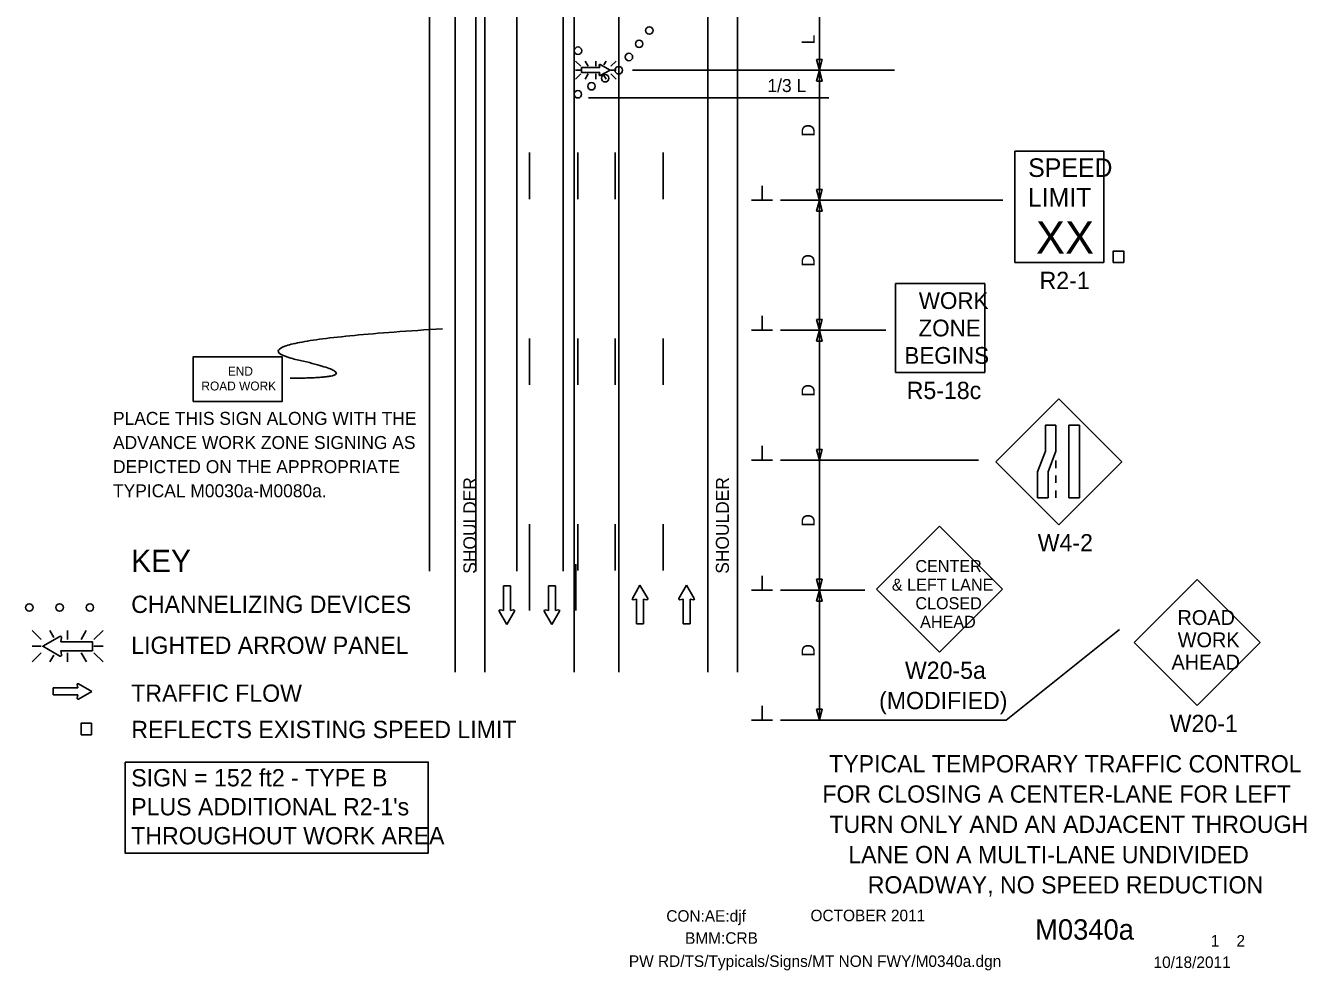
# Model space of a CAD drawing. Extents: x 16743 to 18475, y 7218 to 8262.
# Drawn here: x 16746 to 17435, y 7218 to 7727 of the extents above; entities that cross this region are included whole.
import ezdxf

# ---------------------------------------------------------------- set-up
doc = ezdxf.new("R2010")
doc.units = 0
for name, color, linetype in [('ALI_LEGAL_EX', 7, 'Continuous'), ('BORDER_SIGNAL_WO', 7, 'Continuous'), ('MT_SCRATCH_LEVEL_E', 7, 'Continuous'), ('PAVT_EDGE_EX', 7, 'Continuous'), ('TRAFFIC_SIGNS_PR', 7, 'Continuous'), ('TYPICAL_TEXT_DIMEN_EX', 7, 'Continuous'), ('TYPICAL_TEXT_DIMEN_PR', 7, 'Continuous')]:
    doc.layers.add(name, color=color, linetype=linetype)

msp = doc.modelspace()

# ---------------------------------------------------------------- linework, layer by layer
at = {"layer": 'ALI_LEGAL_EX'}
for points in [[(17017.08, 7658.47), (17017.08, 7633.47)], [(17043.08, 7658.47), (17043.08, 7633.47)], [(17063.08, 7658.47), (17063.08, 7633.47)], [(17089.08, 7658.47), (17089.08, 7633.47)], [(17017.08, 7558.47), (17017.08, 7533.47)], [(17043.08, 7558.47), (17043.08, 7533.47)], [(17063.08, 7558.47), (17063.08, 7533.47)], [(17089.08, 7558.47), (17089.08, 7533.47)], [(17017.08, 7458.47), (17017.08, 7433.47)], [(17043.08, 7458.47), (17043.08, 7433.47)], [(17063.08, 7458.47), (17063.08, 7433.47)], [(17089.08, 7458.47), (17089.08, 7433.47)]]:
    msp.add_lwpolyline(points, dxfattribs=at)
at = {"layer": 'MT_SCRATCH_LEVEL_E'}
for p, q in [((17006.75, 7425.14), (17003.01, 7425.14)), ((17003.01, 7425.14), (17003.01, 7411.89)), ((17006.75, 7425.14), (17003.01, 7425.14)), ((17003.01, 7425.14), (17003.01, 7411.89)), ((17006.75, 7411.89), (17006.75, 7425.14)), ((17006.75, 7411.89), (17006.75, 7425.14)), ((17031.01, 7425.14), (17027.26, 7425.14)), ((17027.26, 7425.14), (17027.26, 7411.89)), ((17031.01, 7425.14), (17027.26, 7425.14)), ((17027.26, 7425.14), (17027.26, 7411.89)), ((17031.01, 7411.89), (17031.01, 7425.14)), ((17031.01, 7411.89), (17031.01, 7425.14)), ((17076.52, 7425.6), (17072.41, 7418.36)), ((17076.52, 7425.6), (17072.41, 7418.36)), ((17080.67, 7418.36), (17076.52, 7425.6)), ((17080.67, 7418.36), (17076.52, 7425.6)), ((17101.61, 7425.6), (17097.5, 7418.36)), ((17101.61, 7425.6), (17097.5, 7418.36)), ((17105.75, 7418.36), (17101.61, 7425.6)), ((17105.75, 7418.36), (17101.61, 7425.6)), ((17072.89, 7417.68), (17074.67, 7417.99)), ((17072.89, 7417.68), (17074.67, 7417.99)), ((17074.67, 7417.99), (17074.67, 7404.74)), ((17074.67, 7417.99), (17074.67, 7404.74)), ((17078.41, 7404.74), (17078.41, 7417.99)), ((17078.41, 7417.99), (17080.19, 7417.68)), ((17078.41, 7404.74), (17078.41, 7417.99)), ((17078.41, 7417.99), (17080.19, 7417.68)), ((17097.98, 7417.68), (17099.76, 7417.99)), ((17097.98, 7417.68), (17099.76, 7417.99)), ((17099.76, 7417.99), (17099.76, 7404.74)), ((17099.76, 7417.99), (17099.76, 7404.74)), ((17103.5, 7404.74), (17103.5, 7417.99)), ((17103.5, 7417.99), (17105.28, 7417.68)), ((17103.5, 7404.74), (17103.5, 7417.99)), ((17103.5, 7417.99), (17105.28, 7417.68)), ((17000.75, 7411.52), (17004.9, 7404.28)), ((17000.75, 7411.52), (17004.9, 7404.28)), ((17003.01, 7411.89), (17001.23, 7412.2)), ((17003.01, 7411.89), (17001.23, 7412.2)), ((17004.9, 7404.28), (17009.01, 7411.52)), ((17004.9, 7404.28), (17009.01, 7411.52)), ((17008.53, 7412.2), (17006.75, 7411.89)), ((17008.53, 7412.2), (17006.75, 7411.89)), ((17025.01, 7411.52), (17029.15, 7404.28)), ((17025.01, 7411.52), (17029.15, 7404.28)), ((17027.26, 7411.89), (17025.49, 7412.2)), ((17027.26, 7411.89), (17025.49, 7412.2)), ((17029.15, 7404.28), (17033.27, 7411.52)), ((17029.15, 7404.28), (17033.27, 7411.52)), ((17032.78, 7412.2), (17031.01, 7411.89)), ((17032.78, 7412.2), (17031.01, 7411.89)), ((17074.67, 7404.74), (17078.41, 7404.74)), ((17074.67, 7404.74), (17078.41, 7404.74)), ((17099.76, 7404.74), (17103.5, 7404.74)), ((17099.76, 7404.74), (17103.5, 7404.74)), ((16773.88, 7370.22), (16760.62, 7370.22)), ((16760.62, 7370.22), (16760.62, 7366.48)), ((16773.88, 7370.22), (16760.62, 7370.22)), ((16760.62, 7370.22), (16760.62, 7366.48)), ((16773.56, 7372), (16773.88, 7370.22)), ((16773.56, 7372), (16773.88, 7370.22)), ((16781.48, 7368.37), (16774.24, 7372.48)), ((16781.48, 7368.37), (16774.24, 7372.48)), ((16760.62, 7366.48), (16773.88, 7366.48)), ((16760.62, 7366.48), (16773.88, 7366.48)), ((16773.88, 7366.48), (16773.56, 7364.7)), ((16773.88, 7366.48), (16773.56, 7364.7)), ((16774.24, 7364.22), (16781.48, 7368.37)), ((16774.24, 7364.22), (16781.48, 7368.37))]:
    msp.add_line(p, q, dxfattribs=at)
for centre, start, end in [((17072.81, 7418.14), 150.42484, 279.96381), ((17072.81, 7418.14), 150.42484, 279.96381), ((17080.26, 7418.14), 260.03619, 29.77312), ((17080.26, 7418.14), 260.03619, 29.77312), ((17097.9, 7418.14), 150.42484, 279.96381), ((17097.9, 7418.14), 150.42484, 279.96381), ((17105.34, 7418.14), 260.03619, 29.77312), ((17105.34, 7418.14), 260.03619, 29.77312), ((17001.16, 7411.74), 80.03619, 209.77312), ((17001.16, 7411.74), 80.03619, 209.77312), ((17008.6, 7411.74), 330.42484, 99.96381), ((17008.6, 7411.74), 330.42484, 99.96381), ((17025.42, 7411.74), 80.03619, 209.77312), ((17025.42, 7411.74), 80.03619, 209.77312), ((17032.86, 7411.74), 330.42484, 99.96381), ((17032.86, 7411.74), 330.42484, 99.96381), ((16774.02, 7372.07), 60.42484, 189.96381), ((16774.02, 7372.07), 60.42484, 189.96381), ((16774.02, 7364.63), 170.03619, 299.77312), ((16774.02, 7364.63), 170.03619, 299.77312)]:
    msp.add_arc(centre, 0.463, start, end, dxfattribs=at)
at = {"layer": 'PAVT_EDGE_EX'}
for p, q in [((16963.15, 8262.34), (16963.15, 7433.15)), ((16988.15, 8262.34), (16988.15, 7433.15)), ((17010.15, 8262.34), (17010.15, 7433.15)), ((17035.15, 8262.34), (17035.15, 7433.15)), ((16977.08, 8216.25), (16977.08, 7378.68)), ((16993.08, 8216.25), (16993.08, 7378.68)), ((17041.08, 8216.25), (17041.08, 7378.68)), ((17065.08, 8216.25), (17065.08, 7378.68)), ((17113.08, 8216.25), (17113.08, 7378.68)), ((17129.08, 8216.25), (17129.08, 7378.68))]:
    msp.add_line(p, q, dxfattribs=at)
for points in [[(17017.08, 7411.93), (17017.08, 7436.93)], [(17042.08, 7411.93), (17042.08, 7436.93)]]:
    msp.add_lwpolyline(points, dxfattribs=at)
at = {"layer": 'TRAFFIC_SIGNS_PR'}
for p, q in [((17044.7, 7705), (17041.88, 7707.82)), ((17047, 7707.82), (17048.62, 7705)), ((17052.78, 7705), (17052.78, 7707.82)), ((17058.25, 7707.82), (17057.05, 7705.72)), ((17063.69, 7707.82), (17060.87, 7705)), ((17044.7, 7702.97), (17041.88, 7702.97)), ((17044.7, 7700.93), (17041.88, 7698.11)), ((17048.65, 7700.93), (17047.02, 7698.11)), ((17052.78, 7700.93), (17052.78, 7698.11)), ((17056.97, 7700.3), (17058.23, 7698.11)), ((17060.87, 7702.97), (17063.69, 7702.97)), ((17063.69, 7698.11), (17060.87, 7700.93)), ((17278.25, 7659.32), (17326.25, 7659.32)), ((17278.25, 7599.32), (17278.25, 7659.32)), ((17326.25, 7599.32), (17326.25, 7659.32)), ((17278.25, 7599.32), (17326.25, 7599.32)), ((17214.07, 7540.09), (17214.07, 7588.09)), ((17214.07, 7588.09), (17262.07, 7588.09)), ((17262.07, 7540.09), (17262.07, 7588.09)), ((17214.07, 7540.09), (17262.07, 7540.09)), ((17301.9, 7525.93), (17267.96, 7491.99)), ((17335.84, 7491.99), (17301.9, 7525.93)), ((17267.96, 7491.99), (17301.9, 7458.05)), ((17300.34, 7492.61), (17300.34, 7488.61)), ((17301.9, 7458.05), (17335.84, 7491.99)), ((17300.34, 7484.61), (17300.34, 7480.61)), ((17300.34, 7476.61), (17300.34, 7472.61)), ((17237.71, 7457.26), (17203.76, 7423.32)), ((17271.65, 7423.32), (17237.71, 7457.26)), ((17376.38, 7428.63), (17342.44, 7394.69)), ((17410.33, 7394.69), (17376.38, 7428.63)), ((17203.76, 7423.32), (17237.71, 7389.38)), ((17237.71, 7389.38), (17271.65, 7423.32)), ((16749.35, 7401.18), (16754.28, 7396.24)), ((16761.11, 7397.36), (16758.9, 7401.18)), ((16768.43, 7396.24), (16768.43, 7401.18)), ((16775.67, 7396.24), (16778.52, 7401.18)), ((16782.58, 7396.24), (16787.52, 7401.18)), ((16754.28, 7392.69), (16749.35, 7392.69)), ((16782.58, 7392.69), (16787.52, 7392.69)), ((17342.44, 7394.69), (17376.38, 7360.74)), ((17376.38, 7360.74), (17410.33, 7394.69)), ((16749.35, 7384.2), (16754.28, 7389.13)), ((16758.86, 7384.2), (16760.97, 7387.86)), ((16768.43, 7389.13), (16768.43, 7384.2)), ((16778.56, 7384.2), (16775.71, 7389.13)), ((16782.58, 7389.13), (16787.52, 7384.2))]:
    msp.add_line(p, q, dxfattribs=at)
for points in [[(17054.61, 7705.65), (17054.84, 7704.35), (17045.12, 7704.35), (17045.12, 7701.61), (17054.84, 7701.61), (17054.61, 7700.3)], [(17055.11, 7699.95), (17060.42, 7702.97), (17055.11, 7706.01)], [(16764.36, 7397.96), (16755.07, 7392.69), (16764.36, 7387.37)], [(16765.23, 7388), (16764.83, 7390.26), (16781.85, 7390.26), (16781.85, 7395.07), (16764.83, 7395.07), (16765.24, 7397.35)]]:
    msp.add_lwpolyline(points, dxfattribs=at)
for points in [[(17331.27, 7599.32), (17336.86, 7599.32), (17336.86, 7605.49), (17331.27, 7605.49)], [(16835.95, 7524.48), (16883.95, 7524.48), (16883.95, 7548.48), (16835.95, 7548.48)], [(17300.34, 7511.66), (17300.34, 7497.69), (17296.16, 7486.58), (17296.16, 7472.61), (17290.54, 7472.61), (17290.54, 7486.58), (17294.72, 7497.69), (17294.72, 7511.66)], [(17313.01, 7511.66), (17313.01, 7472.61), (17307.39, 7472.61), (17307.39, 7511.66)], [(16775.69, 7345.03), (16781.28, 7345.03), (16781.28, 7351.2), (16775.69, 7351.2)]]:
    msp.add_lwpolyline(points, close=True, dxfattribs=at)
for centre in [(17081.56, 7724.23), (17043.18, 7713.37), (17076.07, 7717.1), (17070.57, 7709.97), (17057.75, 7698.54), (17065.08, 7702.84), (17050.42, 7694.23), (17043.1, 7689.92), (16747.86, 7413.53), (16764.16, 7413.53), (16780.46, 7413.53)]:
    msp.add_circle(centre, 2, dxfattribs=at)
for centre, radius, start, end in [((17054.95, 7705.71), 0.341, 61.48329, 189.95933), ((17054.95, 7700.25), 0.341, 170.73078, 298.89165), ((16764.65, 7397.44), 0.598, 350.73078, 118.89165), ((16764.65, 7387.89), 0.597, 241.48329, 9.95933)]:
    msp.add_arc(centre, radius, start, end, dxfattribs=at)
msp.add_open_spline([(16888.26, 7537.03), (16935.5, 7537.03), (16850.48, 7556.38), (16970.27, 7563.62)], degree=2, dxfattribs=at)
at = {"layer": 'TYPICAL_TEXT_DIMEN_EX'}
msp.add_lwpolyline([(16799.36, 7330.3), (16962.52, 7330.3), (16962.52, 7281.28), (16799.36, 7281.28)], close=True, dxfattribs=at)
at = {"layer": 'TYPICAL_TEXT_DIMEN_PR'}
for p, q in [((17173.08, 7702.84), (17173.08, 7733.42)), ((17173.08, 7702.84), (17171.51, 7708.7)), ((17171.51, 7708.7), (17173.08, 7708.7)), ((17173.08, 7708.7), (17174.65, 7708.7)), ((17174.65, 7708.7), (17173.08, 7702.84)), ((17213.45, 7702.84), (17072.44, 7702.84)), ((17171.51, 7696.98), (17173.08, 7702.84)), ((17173.08, 7702.84), (17173.08, 7632.84)), ((17173.08, 7702.84), (17174.65, 7696.98)), ((17173.08, 7696.98), (17171.51, 7696.98)), ((17174.65, 7696.98), (17173.08, 7696.98)), ((17178.08, 7687.92), (17048.76, 7687.92)), ((17142.21, 7632.84), (17142.21, 7640.63)), ((17173.08, 7632.84), (17171.51, 7638.7)), ((17171.51, 7638.7), (17173.08, 7638.7)), ((17173.08, 7638.7), (17174.65, 7638.7)), ((17174.65, 7638.7), (17173.08, 7632.84)), ((17147.83, 7632.84), (17136.58, 7632.84)), ((17271.79, 7632.84), (17152.08, 7632.84)), ((17171.51, 7626.98), (17173.08, 7632.84)), ((17171.51, 7626.98), (17173.08, 7632.84)), ((17173.08, 7632.84), (17173.08, 7562.84)), ((17173.08, 7632.84), (17174.65, 7626.98)), ((17173.08, 7632.84), (17174.65, 7626.98)), ((17173.08, 7626.98), (17171.51, 7626.98)), ((17173.08, 7626.98), (17171.51, 7626.98)), ((17174.65, 7626.98), (17173.08, 7626.98)), ((17174.65, 7626.98), (17173.08, 7626.98)), ((17142.21, 7562.84), (17142.21, 7570.63)), ((17147.83, 7562.84), (17136.58, 7562.84)), ((17208.78, 7562.84), (17152.08, 7562.84)), ((17173.08, 7562.84), (17171.51, 7568.7)), ((17171.51, 7568.7), (17173.08, 7568.7)), ((17171.51, 7556.98), (17173.08, 7562.84)), ((17173.08, 7568.7), (17174.65, 7568.7)), ((17174.65, 7568.7), (17173.08, 7562.84)), ((17173.08, 7562.84), (17173.08, 7492.84)), ((17173.08, 7562.84), (17174.65, 7556.98)), ((17173.08, 7556.98), (17171.51, 7556.98)), ((17174.65, 7556.98), (17173.08, 7556.98)), ((17142.21, 7492.84), (17142.21, 7500.63)), ((17173.08, 7492.84), (17171.51, 7498.7)), ((17171.51, 7498.7), (17173.08, 7498.7)), ((17173.08, 7498.7), (17174.65, 7498.7)), ((17174.65, 7498.7), (17173.08, 7492.84)), ((17147.83, 7492.84), (17136.58, 7492.84)), ((17258.69, 7492.84), (17152.08, 7492.84)), ((17173.08, 7492.84), (17173.08, 7422.84)), ((17142.21, 7422.84), (17142.21, 7430.63)), ((17173.08, 7422.84), (17171.51, 7428.7)), ((17171.51, 7428.7), (17173.08, 7428.7)), ((17173.08, 7428.7), (17174.65, 7428.7)), ((17174.65, 7428.7), (17173.08, 7422.84)), ((17147.83, 7422.84), (17136.58, 7422.84)), ((17197.57, 7422.84), (17152.08, 7422.84)), ((17171.51, 7416.98), (17173.08, 7422.84)), ((17173.08, 7422.84), (17173.08, 7352.84)), ((17173.08, 7422.84), (17174.65, 7416.98)), ((17173.08, 7416.98), (17171.51, 7416.98)), ((17174.65, 7416.98), (17173.08, 7416.98)), ((17273.68, 7352.84), (17334.52, 7401.61)), ((17142.21, 7352.84), (17142.21, 7360.63)), ((17173.08, 7352.84), (17171.51, 7358.7)), ((17171.51, 7358.7), (17173.08, 7358.7)), ((17173.08, 7358.7), (17174.65, 7358.7)), ((17174.65, 7358.7), (17173.08, 7352.84)), ((17147.83, 7352.84), (17136.58, 7352.84)), ((17273.68, 7352.84), (17152.08, 7352.84))]:
    msp.add_line(p, q, dxfattribs=at)

# ---------------------------------------------------------------- texts
at = {"layer": 'BORDER_SIGNAL_WO'}
for s, height, p in [('TYPICAL TEMPORARY TRAFFIC CONTROL', 9.3, (17178.31, 7324.72)), ('FOR CLOSING A CENTER-LANE FOR LEFT', 9.3, (17174.71, 7308.42)), ('TURN ONLY AND AN ADJACENT THROUGH', 9.3, (17178.47, 7292.12)), ('LANE ON A MULTI-LANE UNDIVIDED', 9.3, (17188.63, 7275.82)), ('ROADWAY, NO SPEED REDUCTION', 9.3, (17199.12, 7259.52)), ('CON:AE:djf', 6.2, (17090.69, 7244.31)), ('    OCTOBER 2011    ', 6.2, (17159.08, 7244.59)), ('    M0340a   ', 11, (17272.86, 7234.63)), ('BMM:CRB   ', 6.2, (17100.81, 7232.42)), (' 1    2 ', 6.2, (17381.45, 7230.95)), ('PW RD/TS/Typicals/Signs/MT NON FWY/M0340a.dgn    ', 6.2, (17070.55, 7219.96)), ('10/18/2011    ', 6.2, (17352.93, 7219.38))]:
    msp.add_text(s, height=height, dxfattribs=at).set_placement(p)
at = {"layer": 'TRAFFIC_SIGNS_PR'}
for s, height, p in [('SPEED', 10, (17285.46, 7645.4)), ('LIMIT', 10, (17285.26, 7629.4)), ('XX', 17.538, (17289.64, 7604.02)), ('R2-1', 9.3, (17291.6, 7585.02)), ('WORK', 9.021, (17226.57, 7574.3)), ('ZONE', 9.021, (17226.42, 7559.53)), ('BEGINS', 9.021, (17218.83, 7544.77)), ('END', 4.789, (16854.71, 7538.39)), ('ROAD WORK', 4.789, (16840.47, 7530.41)), ('R5-18c', 9.3, (17220.08, 7525.79)), ('PLACE THIS SIGN ALONG WITH THE', 7, (16792.9, 7511.87)), ('ADVANCE WORK ZONE SIGNING AS', 7, (16792.9, 7498.87)), ('DEPICTED ON THE APPROPRIATE', 7, (16792.9, 7485.87)), ('TYPICAL M0030a-M0080a.', 7, (16792.9, 7472.87)), ('W4-2', 9.3, (17290.6, 7443.75)), ('CENTER', 6.5, (17224.75, 7432.57)), ('& LEFT LANE', 6.5, (17212.09, 7422.57)), ('CLOSED', 6.5, (17224.75, 7412.57)), ('ROAD', 8, (17365.81, 7404.11)), ('AHEAD', 6.5, (17227.28, 7402.57)), ('WORK', 8, (17365.95, 7392.11)), ('W20-5a', 9.3, (17219.13, 7375.07)), ('AHEAD', 8, (17362.58, 7380.11)), ('(MODIFIED)', 9.3, (17205.2, 7358.78)), ('W20-1', 9.3, (17361.6, 7346.45))]:
    msp.add_text(s, height=height, dxfattribs=at).set_placement(p)
at = {"layer": 'TYPICAL_TEXT_DIMEN_EX'}
for s, height, p in [('KEY', 12, (16802.7, 7432.64)), ('CHANNELIZING DEVICES', 9.3, (16802.7, 7410.59)), ('LIGHTED ARROW PANEL', 9.3, (16802.7, 7388.54)), ('TRAFFIC FLOW', 9.3, (16802.7, 7362.74)), ('REFLECTS EXISTING SPEED LIMIT', 9.3, (16802.73, 7343.19)), ('SIGN = 152 ft2 - TYPE B', 9.3, (16802.7, 7317.18)), ("PLUS ADDITIONAL R2-1's", 9.3, (16802.7, 7301.58)), ('THROUGHOUT WORK AREA', 9.3, (16802.7, 7285.98))]:
    msp.add_text(s, height=height, dxfattribs=at).set_placement(p)
at = {"layer": 'TYPICAL_TEXT_DIMEN_PR'}
for s, p in [('L', (17170.52, 7716.71)), ('D', (17170.52, 7667.06)), ('D', (17170.52, 7597.06)), ('D', (17170.52, 7527.06)), ('SHOULDER', (16988.46, 7431.71)), ('SHOULDER', (17124.36, 7431.71)), ('D', (17170.52, 7457.06)), ('D', (17170.52, 7387.06))]:
    msp.add_text(s, height=7, rotation=90, dxfattribs=at).set_placement(p)
msp.add_text('1/3 L', height=7, dxfattribs=at).set_placement((17145.13, 7691.12))

doc.saveas('drawing.dxf')
